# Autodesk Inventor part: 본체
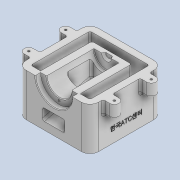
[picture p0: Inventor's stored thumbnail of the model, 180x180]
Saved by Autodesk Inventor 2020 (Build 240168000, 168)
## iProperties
Created: 2022-03
Part Number: 본체
Material: 일반
Document SubType Name: Modeling
Designer: Administrator
Density: 1 g/cm^3
Appearance: 기본값
Author: Administrator
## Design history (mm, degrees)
sketch "스케치1"
  geometry: L1 (-55, 55)-(55, 55); L2 (55, 55)-(55, -55); L3 (55, -55)-(-55, -55); L4 (-55, -55)-(-55, 55); L5 (-55, 55)-(55, -55); L6 (55, 55)-(-55, -55); 1 further point
  constraints: 12 end point, 2 midpoint, 2 parallel, 1 horizontal, 1 perpendicular
  dimensions: "d0" = 110 distance of L1.start L1.end; "d1" = 110 distance of L3.end L1.start
extrude "돌출1" new body sketch "스케치1" distance "d2" = 65; taper "d3" = 0 deg
fillet "모깎기1" dims "d4" = 13
feature "쉘1" dims "d5" = 10
sketch "스케치3"
  geometry: L1 (-55, 0)-(-55, 65) reference; L2 (-55, 65)-(60.016, 65); L3 (33, 65)-(33, 30); L4 (55, 65)-(55, 0) reference; L5 (-55, 6.42)-(33, 30); L6 (-45, 0)-(-45, 65) reference; L7 (42, 0)-(-42, 0) reference; 2 further points
  constraints: 6 end point, 4 point on line, 1 horizontal, 1 vertical
  dimensions: "d14" = 22 distance between parallel lines of L3 L4; "d15" = 75 deg angle of L3 L5; "d19" = 30 distance from line of L3.end L7
sketch "스케치2"
  geometry: L1 (-55, 0)-(-55, 65) reference; L2 (-55, 65)-(69.829, 65); L3 (-55, 65)-(-55, 93); L4 (-55, 93)-(-47, 93); L5 (-47, 93)-(-47, 84); L6 (-47, 84)-(25, 84); L7 (25, 84)-(25, 72.5); L8 (25, 72.5)-(29, 70.191); L9 (29, 70.191)-(29, 65); 1 further point
  constraints: 16 end point, 4 perpendicular, 1 horizontal, 1 parallel, 1 point on line, 1 vertical
  dimensions: "d6" = 56 diameter of L4 L2; "d7" = 38 diameter of L6 L2; "d8" = 30 deg angle of L8 L2; "d10" = 15 diameter of L7.end L2; "d11" = 8 distance of L3.end L4.end; "d12" = 72 distance of L5.end L6.end; "d13" = 4 horizontal distance of L7.end L8.end
extrude "돌출2" join sketch "스케치3" stored distance "d20" = 60; taper "d21" = 0 deg
revolve "회전3" stored, may be unused: angle "d22" = 90 deg
sketch "스케치4"
  geometry: L1 (33, 30)-(-45, 9.1) reference; L2 (19, 31.425)-(-55, 11.597); L3 (-55, 37)-(-55, 65) reference; L4 (-55, 0)-(-55, 65) reference; L5 (25, 46)-(-47, 46) reference; L6 (-19, 38.843)-(-55, 29.197); L7 (-19, 65)-(-19, 38.843); L8 (19, 65)-(19, 31.425); L9 (-47, 65)-(25, 65) reference; 3 further points
  constraints: 8 end point, 8 point on line, 3 parallel, 1 vertical
  dimensions: "d23" = 5 distance between parallel lines of L2 L1; "d27" = 36 distance between parallel lines of L7 L4; "d28" = 38 distance between parallel lines of L8 L7; "d29" = 17 distance between parallel lines of L6 L2
extrude "돌출3" cut sketch "스케치4" stored distance "d30" = 34; taper "d31" = 0 deg
sketch "스케치5"
  geometry: L1 (-65, -35)-(-45, -35); L2 (-45, -35)-(-45, -21); L3 (-45, -21)-(-65, -21); L4 (-65, -21)-(-65, -35); L5 (42, 55)-(-42, 55) reference; L6 (-45, -42)-(-45, 42) reference; L7 (0, 55)-(0, -68.794); L8 (-45, 0)-(-112.804, 0); L9 (-45, 21)-(-65, 21); L10 (-65, 35)-(-45, 35); L11 (-45, 35)-(-45, 21); C1 r 7 at (-65, -28); C2 r 7 at (-65, 28); 8 further points
  constraints: 18 end point, 5 symmetric about line, 3 midpoint, 2 centre point, 2 horizontal, 2 parallel, 1 coincident, 1 collinear, 1 perpendicular, 1 tangent, 1 vertical, 1 other
  dimensions: "d32" = 83 distance from line of C1.centre L5; "d33" = 14 distance of L1.end L2.end; "d34" = 65 distance from line of C2.centre L7; "d37" = 27 distance from line of C2.centre L5 (derived)
extrude "돌출4" join sketch "스케치5" distance "d35" = 20; taper "d36" = 0 deg
sketch "스케치6"
  geometry: A1 r 7 centre (-65, 28) between (-65, 35) and (-65, 21) reference; A2 r 7 centre (-65, -28) between (-65, -21) and (-65, -35) reference; A3 r 7 centre (65, -28) between (65, -35) and (65, -21) reference; A4 r 7 centre (65, 28) between (65, 21) and (65, 35) reference; 5 further points
  constraints: 4 coincident
hole "구멍1" sketch "스케치6" at (-65, 28), (-65, -28), (65, -28), (65, 28) diameter "d38" = 3.242; stored, may be unused: countersink angle "d42" = 90 deg, drill point angle "d44" = 118 deg; dims "d39" = 9, "d40" = 26, "d41" = 10, "d43" = 11
sketch "스케치7"
  geometry: L1 (19, 0)-(28, 0) reference; L2 (-28, 0)-(-19, 0) reference; A1 r 19 centre (0, 0) between (-19, 0) and (19, 0) reference; A2 r 28 centre (0, 0) between (-28, 0) and (28, 0) reference; 2 further points
  constraints: 1 vertical alignment
  dimensions: "d45" = 23 distance of A1.centre point (0, -23)
hole "구멍2" sketch "스케치7" at (0, -23) diameter "d46" = 3.242; stored, may be unused: countersink angle "d50" = 90 deg, drill point angle "d52" = 118 deg; dims "d47" = 9, "d48" = 26, "d49" = 10, "d51" = 11
chamfer "모따기1" distance "d53" = 1; stored, may be unused: second distance "d54" = 2, angle "d55" = 45 deg
fillet "모깎기2" dims "d56" = 3, "d57" = 1
sketch "스케치8"
  geometry: L1 (-65, -13)-(0, -13) reference; 2 further points
  constraints: 1 other
  dimensions: "d58" = 55 distance from line of point (-20, 42) L1; "d59" = 20 distance of point (-20, 42) point (0, 42)
feature "엠보싱1" sketch "스케치8" dims "d0" = 110, "d1" = 110, "d60" = 0.5, "d61" = 0
node "솔리드1"
mirror "미러1"
node "투영된 루프1"
feature "A9D066F2-1C7D-4E18-AEED-F7BC21143FA4" dims "d38" = 3.242, "d39" = 9, "d40" = 26, "d41" = 10, "d42" = 90 deg, "d43" = 11, "d44" = 118 deg
other parameters: "d24" = 17, "d25" = 36, "d26" = 38
